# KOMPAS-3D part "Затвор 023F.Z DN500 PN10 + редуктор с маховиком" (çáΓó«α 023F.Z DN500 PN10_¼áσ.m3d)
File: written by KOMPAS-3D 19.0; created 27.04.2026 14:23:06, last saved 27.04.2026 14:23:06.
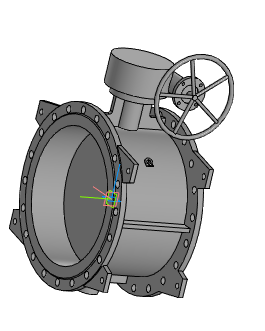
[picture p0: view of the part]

Document properties: Полное имя файла: ..\..\Затвор 023F.Z DN200-DN1600_с маховиком\Затвор 023F.Z DN500 PN10 + редуктор с маховиком.a3d

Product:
- Part/product: Затвор 023F.Z DN500 PN10 + редуктор с маховиком
    Масса: 260.173

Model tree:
1. Операция без истории:1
